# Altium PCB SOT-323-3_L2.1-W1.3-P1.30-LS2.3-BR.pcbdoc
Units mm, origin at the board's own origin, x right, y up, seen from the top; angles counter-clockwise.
Board outline 15.52 x 15.03 mm, 2 copper layers (Top Layer, Bottom Layer), stack 0 mm thick; 1 components, 0 nets, 3 pads, 0 vias.
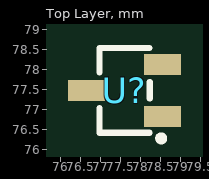
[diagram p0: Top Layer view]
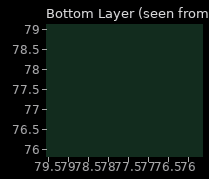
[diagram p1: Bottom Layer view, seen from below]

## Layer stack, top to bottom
Top Layer: signal copper (thickness not stored)
Bottom Layer: signal copper (thickness not stored)

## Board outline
85.369,69.85 69.85,69.85 69.85,84.885 85.369,84.885

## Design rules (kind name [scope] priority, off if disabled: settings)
PasteMaskExpansion "Paste Mask Expansion" [All] p1: expansion=0
SolderMaskExpansion "Solder Mask Expansion" [IsVia] p1: expansion=-25.4 istentingtop=TRUE
SolderMaskExpansion "Solder Mask Expansion" [All] p2: expansion=0.051 istentingtop=FALSE

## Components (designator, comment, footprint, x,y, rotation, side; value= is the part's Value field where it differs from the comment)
U? "" SOT-323-3_L2.1-W1.3-P1.30-LS2.3-BR 77.609,77.475 r0 top

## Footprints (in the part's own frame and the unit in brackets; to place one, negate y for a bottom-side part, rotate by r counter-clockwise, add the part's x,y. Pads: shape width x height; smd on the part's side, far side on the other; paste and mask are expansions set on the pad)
SOT-323-3_L2.1-W1.3-P1.30-LS2.3-BR [mm]
  rect 0.919x0.525 smd: 1(0.95,-0.65) 2(0.95,0.65) 3(-0.95,0)
  silkscreen extent -0.62,-1.27 0.99,1.06

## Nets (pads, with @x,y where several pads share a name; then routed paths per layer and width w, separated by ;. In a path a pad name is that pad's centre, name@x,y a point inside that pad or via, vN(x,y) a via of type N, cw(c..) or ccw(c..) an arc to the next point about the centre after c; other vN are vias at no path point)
pads on no net: U?.1 U?.2 U?.3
